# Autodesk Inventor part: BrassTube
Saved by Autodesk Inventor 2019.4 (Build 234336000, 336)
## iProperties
Created: 2020-02
Part Number: BrassTube
Material: Generic
Document SubType Name: Modeling
Designer: Administrator
Density: 1 g/cm^3
Appearance: Default
Title: BrassTube v3
Author: Administrator
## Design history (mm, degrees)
feature "Body1"
body "Solid1"
